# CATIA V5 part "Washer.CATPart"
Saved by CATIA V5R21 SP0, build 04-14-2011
Part number: washer
Bounding box of the stored display mesh (mm): x -24 to 24, y -23.825 to 23.825, z 0 to 3
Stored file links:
  D:\CATIA V5R21 E-RESOURCES\CATIA-V5R21\catia-v5r21-Prts\c12_catia_v5r21_prt\c12_catia_v5r21figr_12-54 to 56\Washer.CATPart
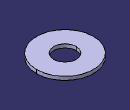
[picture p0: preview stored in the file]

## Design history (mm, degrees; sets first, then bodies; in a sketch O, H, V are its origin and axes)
Body1 (main body)
  Sketch1 on xy-plane, origin (0, 0, 0), H (1, 0, 0), V (0, 1, 0)
    circle A1 centre (0, 0) radius 24
    circle A2 centre (0, 0) radius 9.5
    radius A1 = 24
    radius A2 = 9.5
  Pad1: profile Sketch1, direction (0, 0, 1), length 3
